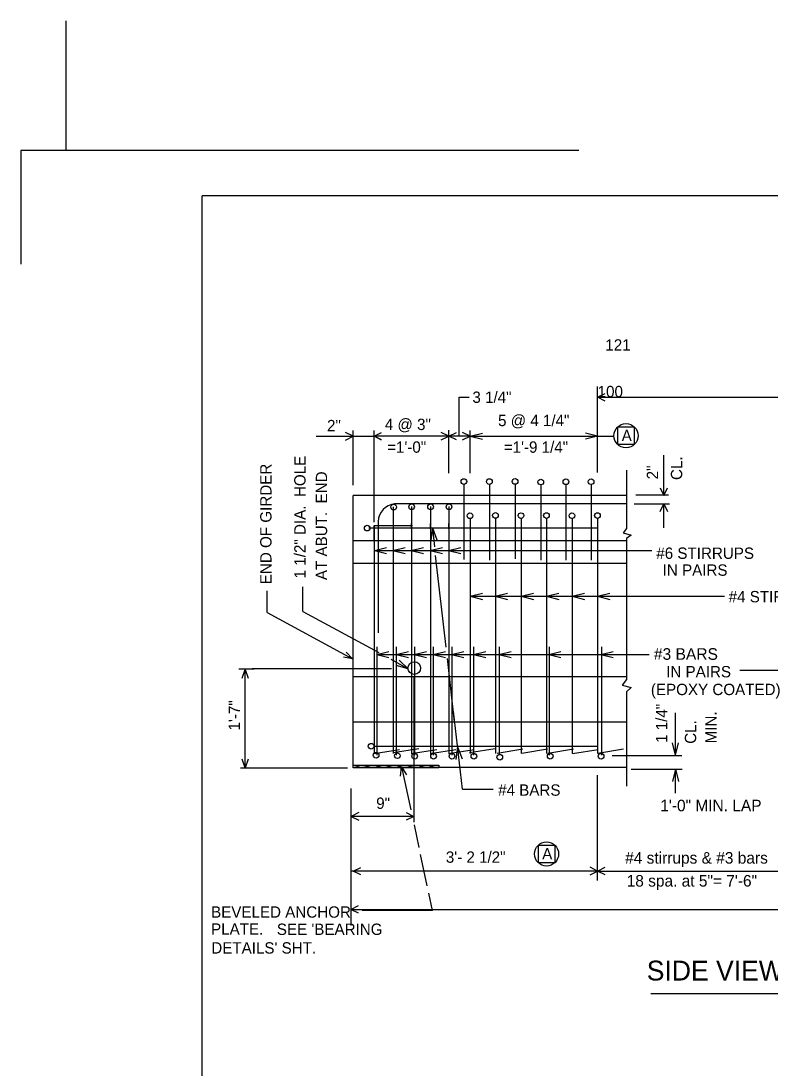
# Model space of a CAD drawing. Extents: x 1005 to 1123, y 2008 to 2074.
# Drawn here: x 1008.66 to 1030.68, y 2043.4 to 2074.18 of the extents above; entities that cross this region are included whole.
import ezdxf

# ---------------------------------------------------------------- set-up
doc = ezdxf.new("R2010")
doc.units = 0
for name, color, linetype in [('Level 1', 7, 'Continuous'), ('Level 2', 7, 'Continuous'), ('Level 5', 7, 'Continuous'), ('Level 6', 7, 'Continuous'), ('Level 60', 7, 'Continuous')]:
    doc.layers.add(name, color=color, linetype=linetype)

msp = doc.modelspace()

# ---------------------------------------------------------------- linework, layer by layer
at = {"layer": 'Level 1'}
for p, q in [((1025.057, 2070.374), (1008.656, 2070.374)), ((1008.656, 2070.374), (1008.656, 2067.034)), ((1013.989, 2013.041), (1013.989, 2069.04)), ((1097.657, 2069.04), (1013.989, 2069.04))]:
    msp.add_line(p, q, dxfattribs=at)
at = {"layer": 'Level 2'}
for p, q in [((1009.989, 2070.374), (1009.989, 2074.178)), ((1025.614, 2060.904), (1025.614, 2063.43)), ((1021.537, 2061.975), (1021.537, 2063.122)), ((1021.537, 2063.122), (1021.839, 2063.122)), ((1025.617, 2063.119), (1052.076, 2063.119)), ((1018.426, 2060.537), (1018.426, 2062.142)), ((1019.039, 2059.444), (1019.039, 2062.142)), ((1021.239, 2060.885), (1021.239, 2062.153)), ((1021.864, 2060.891), (1021.864, 2062.142)), ((1026.698, 2062.239), (1026.198, 2062.239)), ((1026.198, 2062.239), (1026.198, 2061.739)), ((1026.698, 2061.739), (1026.698, 2062.239)), ((1019.039, 2061.97), (1017.341, 2061.97)), ((1021.864, 2061.975), (1019.039, 2061.975)), ((1021.864, 2061.975), (1022.224, 2062.065)), ((1021.864, 2061.975), (1026.089, 2061.975)), ((1021.864, 2061.975), (1022.224, 2061.885)), ((1025.614, 2061.975), (1025.254, 2062.065)), ((1025.614, 2061.975), (1025.254, 2062.065)), ((1025.614, 2061.975), (1025.254, 2061.885)), ((1025.614, 2061.975), (1025.254, 2061.885)), ((1026.198, 2061.739), (1026.698, 2061.739)), ((1026.202, 2061.739), (1026.202, 2061.739)), ((1027.559, 2060.236), (1027.559, 2061.418)), ((1026.466, 2060.978), (1026.466, 2059.266)), ((1021.679, 2060.562), (1021.679, 2058.351)), ((1023.19, 2060.581), (1023.19, 2058.37)), ((1022.434, 2060.543), (1022.434, 2058.332)), ((1023.946, 2060.543), (1023.946, 2058.332)), ((1024.683, 2060.543), (1024.683, 2058.332)), ((1025.42, 2060.543), (1025.42, 2058.332)), ((1026.735, 2060.247), (1027.702, 2060.247)), ((1026.466, 2060.236), (1018.426, 2060.236)), ((1018.426, 2052.307), (1018.426, 2060.236)), ((1026.466, 2059.986), (1019.644, 2059.986)), ((1026.689, 2059.986), (1027.725, 2059.986)), ((1027.559, 2059.277), (1027.559, 2059.986)), ((1019.599, 2059.895), (1019.599, 2053.827)), ((1020.14, 2059.905), (1020.14, 2052.647)), ((1020.696, 2059.905), (1020.696, 2052.647)), ((1021.239, 2059.905), (1021.239, 2052.647)), ((1019.039, 2058.922), (1019.039, 2059.35)), ((1019.039, 2059.347), (1020.169, 2059.347)), ((1019.039, 2059.347), (1019.039, 2052.647)), ((1019.158, 2059.468), (1019.158, 2056.196)), ((1020.14, 2059.25), (1020.14, 2059.411)), ((1020.696, 2059.25), (1020.696, 2059.411)), ((1021.239, 2059.25), (1021.239, 2059.411)), ((1021.864, 2059.541), (1021.864, 2052.647)), ((1022.614, 2059.56), (1022.614, 2052.647)), ((1023.364, 2059.56), (1023.364, 2052.647)), ((1024.114, 2059.57), (1024.114, 2052.647)), ((1024.864, 2059.551), (1024.864, 2052.647)), ((1025.614, 2059.56), (1025.614, 2052.647)), ((1018.885, 2059.28), (1025.614, 2059.28)), ((1020.754, 2059.28), (1020.705, 2058.912)), ((1020.754, 2059.28), (1020.884, 2058.932)), ((1020.754, 2059.28), (1020.817, 2058.725)), ((1026.466, 2059.266), (1026.367, 2059.134)), ((1026.367, 2059.134), (1026.598, 2059.068)), ((1026.598, 2059.068), (1026.466, 2058.97)), ((1026.466, 2058.903), (1018.426, 2058.903)), ((1019.048, 2058.616), (1019.408, 2058.706)), ((1019.59, 2058.616), (1019.95, 2058.706)), ((1020.129, 2058.616), (1020.489, 2058.706)), ((1020.688, 2058.616), (1021.048, 2058.706)), ((1021.229, 2058.616), (1021.589, 2058.706)), ((1026.466, 2058.97), (1026.466, 2054.82)), ((1019.048, 2058.616), (1019.76, 2058.616)), ((1019.048, 2058.616), (1019.408, 2058.526)), ((1019.59, 2058.616), (1019.95, 2058.526)), ((1019.759, 2058.616), (1020.47, 2058.616)), ((1020.129, 2058.616), (1020.489, 2058.526)), ((1020.445, 2058.616), (1027.209, 2058.616)), ((1020.688, 2058.616), (1021.048, 2058.526)), ((1021.156, 2055.779), (1020.847, 2058.47)), ((1021.229, 2058.616), (1021.589, 2058.526)), ((1026.466, 2058.235), (1018.426, 2058.235)), ((1015.896, 2056.792), (1015.896, 2057.432)), ((1021.864, 2057.269), (1022.224, 2057.359)), ((1021.864, 2057.269), (1022.617, 2057.269)), ((1021.864, 2057.269), (1022.224, 2057.179)), ((1022.605, 2057.269), (1022.965, 2057.359)), ((1022.605, 2057.269), (1022.965, 2057.179)), ((1022.617, 2057.269), (1023.366, 2057.269)), ((1023.366, 2057.269), (1023.726, 2057.359)), ((1023.366, 2057.269), (1024.114, 2057.269)), ((1023.366, 2057.269), (1023.726, 2057.179)), ((1024.114, 2057.269), (1024.474, 2057.359)), ((1024.114, 2057.269), (1024.863, 2057.269)), ((1024.114, 2057.269), (1024.474, 2057.179)), ((1024.863, 2057.269), (1025.223, 2057.359)), ((1024.863, 2057.269), (1025.636, 2057.269)), ((1024.863, 2057.269), (1025.223, 2057.179)), ((1025.614, 2057.269), (1025.974, 2057.359)), ((1025.614, 2057.269), (1025.974, 2057.179)), ((1025.636, 2057.269), (1029.34, 2057.269)), ((1015.896, 2056.792), (1018.401, 2055.433)), ((1019.117, 2055.559), (1019.477, 2055.649)), ((1019.123, 2055.784), (1019.123, 2052.602)), ((1019.69, 2055.559), (1020.05, 2055.649)), ((1019.693, 2055.784), (1019.693, 2052.602)), ((1020.22, 2055.559), (1020.58, 2055.649)), ((1020.225, 2055.784), (1020.225, 2052.602)), ((1020.78, 2055.559), (1021.14, 2055.649)), ((1020.782, 2055.784), (1020.782, 2052.602)), ((1021.32, 2055.559), (1021.68, 2055.649)), ((1021.324, 2055.784), (1021.324, 2052.602)), ((1021.963, 2055.559), (1022.323, 2055.649)), ((1021.968, 2055.784), (1021.968, 2052.602)), ((1022.711, 2055.559), (1023.071, 2055.649)), ((1022.716, 2055.784), (1022.716, 2052.602)), ((1024.175, 2055.559), (1024.535, 2055.649)), ((1024.189, 2055.784), (1024.189, 2052.602)), ((1025.711, 2055.559), (1026.071, 2055.649)), ((1025.724, 2055.784), (1025.724, 2052.602)), ((1019.117, 2055.559), (1019.477, 2055.469)), ((1019.123, 2055.559), (1019.884, 2055.559)), ((1019.69, 2055.559), (1020.05, 2055.469)), ((1019.884, 2055.559), (1020.595, 2055.559)), ((1020.22, 2055.559), (1020.58, 2055.469)), ((1020.595, 2055.559), (1022.005, 2055.559)), ((1020.78, 2055.559), (1021.14, 2055.469)), ((1021.408, 2053.583), (1021.195, 2055.44)), ((1021.32, 2055.559), (1021.68, 2055.469)), ((1021.963, 2055.559), (1022.323, 2055.469)), ((1022.005, 2055.559), (1022.754, 2055.559)), ((1022.711, 2055.559), (1023.071, 2055.469)), ((1022.754, 2055.559), (1024.189, 2055.559)), ((1024.175, 2055.559), (1024.535, 2055.469)), ((1024.189, 2055.559), (1025.711, 2055.559)), ((1025.711, 2055.559), (1027.129, 2055.559)), ((1025.711, 2055.559), (1026.071, 2055.469)), ((1031.215, 2055.084), (1029.798, 2055.084)), ((1026.466, 2054.902), (1018.426, 2054.902)), ((1026.466, 2054.82), (1026.334, 2054.656)), ((1026.334, 2054.656), (1026.598, 2054.59)), ((1026.598, 2054.59), (1026.466, 2054.458)), ((1026.466, 2054.458), (1026.466, 2051.69)), ((1019.599, 2053.827), (1019.599, 2052.647)), ((1021.636, 2051.601), (1021.372, 2053.896)), ((1027.901, 2052.603), (1027.901, 2053.841)), ((1026.466, 2053.568), (1018.426, 2053.568)), ((1019.039, 2052.863), (1025.614, 2052.863)), ((1027.901, 2052.603), (1027.811, 2052.963)), ((1027.901, 2052.603), (1027.991, 2052.963)), ((1019.039, 2052.647), (1019.792, 2052.768)), ((1019.599, 2052.674), (1020.352, 2052.795)), ((1020.131, 2052.647), (1020.884, 2052.768)), ((1020.687, 2052.647), (1021.441, 2052.768)), ((1021.23, 2052.647), (1021.983, 2052.768)), ((1021.493, 2052.842), (1021.447, 2052.474)), ((1021.493, 2052.842), (1021.626, 2052.495)), ((1021.85, 2052.674), (1022.603, 2052.795)), ((1022.657, 2052.661), (1023.411, 2052.782)), ((1023.384, 2052.661), (1024.137, 2052.782)), ((1024.151, 2052.661), (1024.904, 2052.782)), ((1024.877, 2052.647), (1025.63, 2052.768)), ((1025.617, 2052.661), (1026.37, 2052.782)), ((1026.04, 2052.595), (1028.087, 2052.595)), ((1018.426, 2052.307), (1018.672, 2052.234)), ((1026.466, 2052.234), (1018.672, 2052.234)), ((1025.614, 2048.921), (1025.614, 2052.008)), ((1026.597, 2052.193), (1028.103, 2052.193)), ((1027.901, 2052.187), (1027.811, 2051.827)), ((1027.901, 2051.479), (1027.901, 2052.187)), ((1027.901, 2052.187), (1027.991, 2051.827)), ((1018.361, 2051.625), (1018.361, 2047.594)), ((1021.636, 2051.601), (1022.542, 2051.601)), ((1024.361, 2049.947), (1023.861, 2049.947)), ((1023.861, 2049.947), (1023.861, 2049.447)), ((1024.361, 2049.447), (1024.361, 2049.947)), ((1025.614, 2049.196), (1018.361, 2049.196)), ((1023.861, 2049.447), (1024.361, 2049.447)), ((1023.866, 2049.447), (1023.866, 2049.447)), ((1025.614, 2049.196), (1033.237, 2049.196)), ((1018.361, 2048.066), (1057.695, 2048.066)), ((1027.181, 2045.596), (1043.723, 2045.596))]:
    msp.add_line(p, q, dxfattribs=at)
for points in [[(1025.836, 2063.008), (1025.614, 2063.119), (1025.836, 2063.23)], [(1019.261, 2061.864), (1019.039, 2061.975), (1019.261, 2062.087)], [(1021.016, 2061.864), (1021.238, 2061.975), (1021.016, 2062.086)], [(1021.461, 2061.864), (1021.239, 2061.975), (1021.461, 2062.086)], [(1021.641, 2061.864), (1021.864, 2061.975), (1021.641, 2062.087)], [(1018.201, 2061.859), (1018.423, 2061.971), (1018.201, 2062.082)], [(1019.263, 2061.859), (1019.041, 2061.971), (1019.263, 2062.082)], [(1021.869, 2061.973), (1021.864, 2061.975), (1021.869, 2061.978)], [(1025.608, 2061.973), (1025.614, 2061.975), (1025.608, 2061.978)], [(1027.448, 2060.458), (1027.559, 2060.236), (1027.67, 2060.458)], [(1027.448, 2059.764), (1027.559, 2059.986), (1027.67, 2059.764)], [(1018.22, 2055.631), (1018.401, 2055.433), (1018.137, 2055.477)], [(1018.648, 2049.081), (1018.426, 2049.192), (1018.648, 2049.303)], [(1025.39, 2049.084), (1025.612, 2049.195), (1025.39, 2049.306)], [(1025.837, 2049.084), (1025.614, 2049.195), (1025.837, 2049.306)], [(1018.584, 2047.955), (1018.361, 2048.066), (1018.584, 2048.178)]]:
    msp.add_lwpolyline(points, dxfattribs=at)
for centre, radius in [((1026.448, 2061.989), 0.354), ((1021.68, 2060.641), 0.0833), ((1022.431, 2060.64), 0.0833), ((1023.186, 2060.644), 0.0833), ((1023.942, 2060.627), 0.0833), ((1024.681, 2060.633), 0.0833), ((1025.421, 2060.637), 0.0833), ((1019.617, 2059.891), 0.0833), ((1020.145, 2059.899), 0.0833), ((1020.701, 2059.899), 0.0833), ((1021.243, 2059.899), 0.0833), ((1021.859, 2059.637), 0.0833), ((1022.609, 2059.646), 0.0833), ((1023.359, 2059.64), 0.0833), ((1024.109, 2059.642), 0.0833), ((1024.859, 2059.638), 0.0833), ((1025.609, 2059.642), 0.0833), ((1018.837, 2059.273), 0.0833), ((1018.953, 2052.863), 0.0833), ((1019.099, 2052.599), 0.0833), ((1019.724, 2052.584), 0.0833), ((1020.232, 2052.569), 0.0833), ((1020.788, 2052.569), 0.0833), ((1021.33, 2052.569), 0.0833), ((1021.974, 2052.569), 0.0833), ((1022.737, 2052.54), 0.0833), ((1024.218, 2052.569), 0.0833), ((1025.715, 2052.569), 0.0833), ((1024.111, 2049.697), 0.354)]:
    msp.add_circle(centre, radius, dxfattribs=at)
msp.add_arc((1019.708, 2059.44), 0.55, 96.657, 177.0425, dxfattribs=at)
at = {"layer": 'Level 5'}
for p, q in [((1016.949, 2056.82), (1016.949, 2057.543)), ((1016.949, 2056.82), (1019.176, 2055.613)), ((1019.531, 2055.421), (1020.047, 2055.141)), ((1020.047, 2055.141), (1019.773, 2055.391)), ((1015.065, 2055.136), (1015.511, 2055.136)), ((1015.245, 2052.225), (1015.245, 2055.116)), ((1019.548, 2055.136), (1015.453, 2055.136)), ((1020.047, 2055.141), (1019.688, 2055.233)), ((1020.204, 2054.903), (1020.204, 2050.634)), ((1018.255, 2052.22), (1015.11, 2052.22)), ((1020.204, 2050.8), (1018.37, 2050.8))]:
    msp.add_line(p, q, dxfattribs=at)
for points in [[(1015.158, 2054.862), (1015.245, 2055.116), (1015.333, 2054.862)], [(1015.158, 2054.862), (1015.245, 2055.116), (1015.333, 2054.862)], [(1015.333, 2052.479), (1015.245, 2052.225), (1015.158, 2052.479)], [(1018.593, 2050.911), (1018.37, 2050.8), (1018.593, 2050.689)], [(1019.981, 2050.911), (1020.204, 2050.8), (1019.981, 2050.689)]]:
    msp.add_lwpolyline(points, dxfattribs=at)
msp.add_circle((1020.221, 2055.158), 0.186, dxfattribs=at)
at = {"layer": 'Level 6'}
for p, q in [((1018.726, 2052.307), (1018.972, 2052.234)), ((1019.057, 2052.307), (1019.304, 2052.234)), ((1019.366, 2052.307), (1019.612, 2052.234)), ((1019.677, 2052.307), (1019.923, 2052.234)), ((1019.85, 2052.253), (1020.119, 2050.997)), ((1019.994, 2052.307), (1020.241, 2052.234)), ((1020.323, 2052.307), (1020.569, 2052.234)), ((1020.623, 2052.307), (1020.869, 2052.234)), ((1020.215, 2050.552), (1020.359, 2049.883)), ((1020.599, 2048.761), (1020.401, 2049.684)), ((1020.756, 2048.032), (1020.646, 2048.542)), ((1020.756, 2048.032), (1018.688, 2048.032))]:
    msp.add_line(p, q, dxfattribs=at)
msp.add_lwpolyline([(1018.424, 2052.307), (1020.946, 2052.307), (1020.946, 2052.231), (1018.424, 2052.231)], close=True, dxfattribs=at)
msp.add_lwpolyline([(1019.817, 2051.987), (1019.85, 2052.253), (1019.989, 2052.023)], dxfattribs=at)

# ---------------------------------------------------------------- texts
at = {"layer": 'Level 2'}
for s, height, p in [('3 1/4"', 0.3333, (1021.931, 2062.953)), ('2"', 0.3333, (1017.657, 2062.12)), ('4 @ 3" ', 0.3333, (1019.356, 2062.155)), ('5 @ 4 1/4"', 0.3333, (1022.686, 2062.27)), ('A', 0.333, (1026.32, 2061.829)), ('=1\'-0"', 0.3333, (1019.424, 2061.488)), ('3\'-9"', 0.00833, (1021.889, 2061.98)), ('=1\'-9 1/4"', 0.3333, (1022.854, 2061.488)), ('#6 STIRRUPS', 0.33333, (1027.339, 2058.369)), ('IN PAIRS', 0.3333, (1027.526, 2057.873)), ('#4 STIRRUPS', 0.33333, (1029.466, 2057.092)), ('#3 BARS', 0.3423, (1027.268, 2055.402)), ('IN PAIRS', 0.3333, (1027.629, 2054.887)), ('(EPOXY COATED)', 0.33333, (1027.179, 2054.365)), ('#4 BARS', 0.3333, (1022.688, 2051.408)), ('1\'-0" MIN. LAP', 0.34001, (1027.456, 2050.951)), ('3\'- 2 1/2"', 0.3333, (1021.15, 2049.438)), ('A', 0.333, (1023.983, 2049.537)), ('#4 stirrups & #3 bars', 0.34001, (1026.423, 2049.412)), ('18 spa. at 5"= 7\'-6"', 0.34001, (1026.467, 2048.738)), (' SIDE VIEW & TYP. SECTION', 0.58333, (1026.841, 2045.978))]:
    msp.add_text(s, height=height, dxfattribs=at).set_placement(p)
for s, height, p in [('CL.', 0.3333, (1028.1, 2060.686)), ('END OF GIRDER', 0.33333, (1016.024, 2057.624)), ('2"', 0.3333, (1027.392, 2060.707)), ('1 1/4"', 0.3333, (1027.663, 2052.959)), ('MIN.', 0.3333, (1029.11, 2052.946)), ('CL.', 0.3333, (1028.511, 2052.934))]:
    msp.add_text(s, height=height, rotation=90, dxfattribs=at).set_placement(p)
at = {"layer": 'Level 5'}
for s, height, p in [('1 1/2" DIA.  HOLE', 0.33333, (1017.026, 2057.797)), ('AT ABUT.  END', 0.33333, (1017.659, 2057.745)), ('1\'-7"', 0.3333, (1015.096, 2053.326))]:
    msp.add_text(s, height=height, rotation=90, dxfattribs=at).set_placement(p)
msp.add_text('9"', height=0.3333, dxfattribs=at).set_placement((1019.102, 2051.021))
at = {"layer": 'Level 6'}
for s, height, p in [('BEVELED ANCHOR', 0.33333, (1014.247, 2047.824)), ('PLATE.', 0.3333, (1014.247, 2047.324)), ("SEE 'BEARING", 0.33333, (1016.181, 2047.317)), ("DETAILS' SHT.", 0.33333, (1014.254, 2046.769))]:
    msp.add_text(s, height=height, dxfattribs=at).set_placement(p)
at = {"layer": 'Level 60'}
for s, p in [('121', (1025.84, 2064.489)), ('100', (1025.614, 2063.119))]:
    msp.add_text(s, height=0.3333, dxfattribs=at).set_placement(p)

doc.saveas('drawing.dxf')
